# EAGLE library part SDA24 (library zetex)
DIODE ARRAY
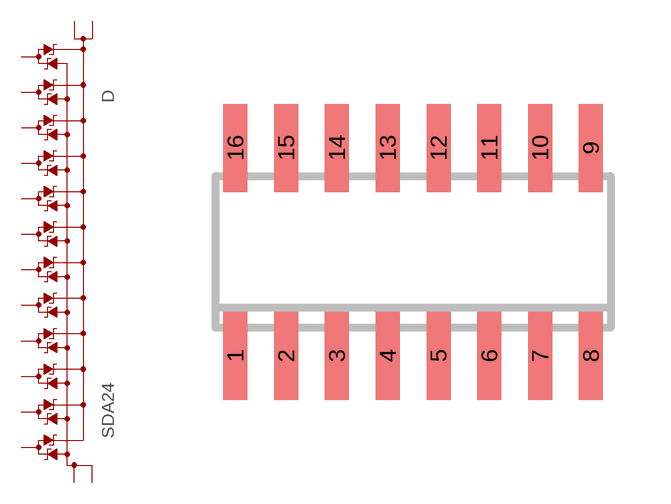
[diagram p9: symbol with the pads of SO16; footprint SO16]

Designator prefix D

## SDA24 (OC_FARNELL: unknown; OC_NEWARK: unknown)  [SO16]
1  V+  pas
2  D01  pas
3  D02  pas
4  D03  pas
5  D04  pas
6  D05  pas
7  D06  pas
8  V-  pas
9  V-1  pas
10  D07  pas
11  D08  pas
12  D09  pas
13  D10  pas
14  D11  pas
15  D12  pas
16  V+1  pas

## Footprint SO16 (pad centres in mm)
SMALL OUTLINE INTEGRATED CIRCUIT body 3.9 mm/JEDEC MS-012AC
smd 0.6 x 2.2: 1 -4.445,-2.6; 2 -3.175,-2.6; 3 -1.905,-2.6; 4 -0.635,-2.6; 5 0.635,-2.6; 6 1.905,-2.6; 7 3.175,-2.6; 8 4.445,-2.6; 9 4.445,2.6; 10 3.175,2.6; 11 1.905,2.6; 12 0.635,2.6; 13 -0.635,2.6; 14 -1.905,2.6; 15 -3.175,2.6; 16 -4.445,2.6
